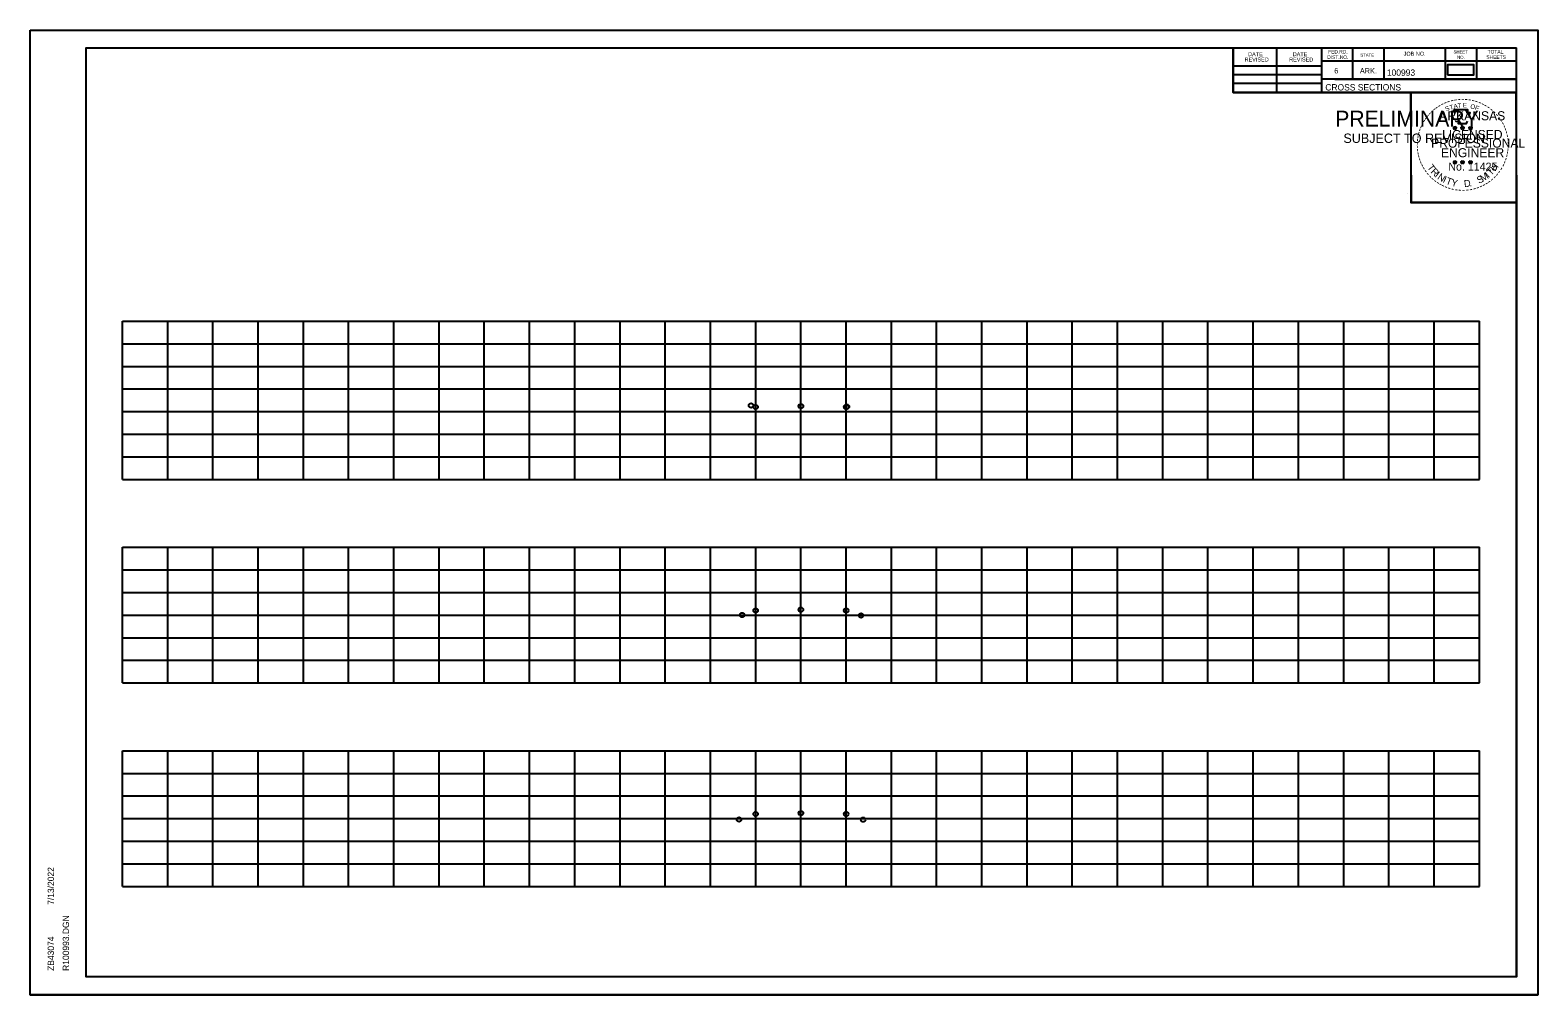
# Model space of a CAD drawing. Extents: x 4667 to 1632277, y -2100 to 724501.
# Drawn here: x 7113.9 to 7447.2, y -782.3 to -569 of the extents above; entities that cross this region are included whole.
import ezdxf

# ---------------------------------------------------------------- set-up
doc = ezdxf.new("R2010")
doc.units = 0
doc.layers.add('R_Grid', color=7, linetype='Continuous')
doc.layers.add('R_No Plot', color=7, linetype='Continuous')

msp = doc.modelspace()

# ---------------------------------------------------------------- linework, layer by layer
at = {"layer": 'R_Grid'}
for p, q in [((7134.28, -633.33), (7434.28, -633.33)), ((7134.28, -668.33), (7134.28, -633.33)), ((7144.28, -668.33), (7144.28, -633.33)), ((7154.28, -668.33), (7154.28, -633.33)), ((7164.28, -668.33), (7164.28, -633.33)), ((7174.28, -668.33), (7174.28, -633.33)), ((7184.28, -668.33), (7184.28, -633.33)), ((7194.28, -668.33), (7194.28, -633.33)), ((7204.28, -668.33), (7204.28, -633.33)), ((7214.28, -668.33), (7214.28, -633.33)), ((7224.28, -668.33), (7224.28, -633.33)), ((7234.28, -668.33), (7234.28, -633.33)), ((7244.28, -668.33), (7244.28, -633.33)), ((7254.28, -668.33), (7254.28, -633.33)), ((7264.28, -668.33), (7264.28, -633.33)), ((7274.28, -668.33), (7274.28, -633.33)), ((7284.28, -668.33), (7284.28, -633.33)), ((7294.28, -668.33), (7294.28, -633.33)), ((7304.28, -668.33), (7304.28, -633.33)), ((7314.28, -668.33), (7314.28, -633.33)), ((7324.28, -668.33), (7324.28, -633.33)), ((7334.28, -668.33), (7334.28, -633.33)), ((7344.28, -668.33), (7344.28, -633.33)), ((7354.28, -668.33), (7354.28, -633.33)), ((7364.28, -668.33), (7364.28, -633.33)), ((7374.28, -668.33), (7374.28, -633.33)), ((7384.28, -668.33), (7384.28, -633.33)), ((7394.28, -668.33), (7394.28, -633.33)), ((7404.28, -668.33), (7404.28, -633.33)), ((7414.28, -668.33), (7414.28, -633.33)), ((7424.28, -668.33), (7424.28, -633.33)), ((7434.28, -668.33), (7434.28, -633.33)), ((7134.28, -638.33), (7434.28, -638.33)), ((7134.28, -643.33), (7434.28, -643.33)), ((7134.28, -648.33), (7434.28, -648.33)), ((7134.28, -653.33), (7434.28, -653.33)), ((7134.28, -658.33), (7434.28, -658.33)), ((7134.28, -663.33), (7434.28, -663.33)), ((7134.28, -668.33), (7434.28, -668.33)), ((7134.28, -683.33), (7434.28, -683.33)), ((7134.28, -713.33), (7134.28, -683.33)), ((7144.28, -713.33), (7144.28, -683.33)), ((7154.28, -713.33), (7154.28, -683.33)), ((7164.28, -713.33), (7164.28, -683.33)), ((7174.28, -713.33), (7174.28, -683.33)), ((7184.28, -713.33), (7184.28, -683.33)), ((7194.28, -713.33), (7194.28, -683.33)), ((7204.28, -713.33), (7204.28, -683.33)), ((7214.28, -713.33), (7214.28, -683.33)), ((7224.28, -713.33), (7224.28, -683.33)), ((7234.28, -713.33), (7234.28, -683.33)), ((7244.28, -713.33), (7244.28, -683.33)), ((7254.28, -713.33), (7254.28, -683.33)), ((7264.28, -713.33), (7264.28, -683.33)), ((7274.28, -713.33), (7274.28, -683.33)), ((7284.28, -713.33), (7284.28, -683.33)), ((7294.28, -713.33), (7294.28, -683.33)), ((7304.28, -713.33), (7304.28, -683.33)), ((7314.28, -713.33), (7314.28, -683.33)), ((7324.28, -713.33), (7324.28, -683.33)), ((7334.28, -713.33), (7334.28, -683.33)), ((7344.28, -713.33), (7344.28, -683.33)), ((7354.28, -713.33), (7354.28, -683.33)), ((7364.28, -713.33), (7364.28, -683.33)), ((7374.28, -713.33), (7374.28, -683.33)), ((7384.28, -713.33), (7384.28, -683.33)), ((7394.28, -713.33), (7394.28, -683.33)), ((7404.28, -713.33), (7404.28, -683.33)), ((7414.28, -713.33), (7414.28, -683.33)), ((7424.28, -713.33), (7424.28, -683.33)), ((7434.28, -713.33), (7434.28, -683.33)), ((7134.28, -688.33), (7434.28, -688.33)), ((7134.28, -693.33), (7434.28, -693.33)), ((7134.28, -698.33), (7434.28, -698.33)), ((7134.28, -703.33), (7434.28, -703.33)), ((7134.28, -708.33), (7434.28, -708.33)), ((7134.28, -713.33), (7434.28, -713.33)), ((7134.28, -728.33), (7434.28, -728.33)), ((7134.28, -758.33), (7134.28, -728.33)), ((7144.28, -758.33), (7144.28, -728.33)), ((7154.28, -758.33), (7154.28, -728.33)), ((7164.28, -758.33), (7164.28, -728.33)), ((7174.28, -758.33), (7174.28, -728.33)), ((7184.28, -758.33), (7184.28, -728.33)), ((7194.28, -758.33), (7194.28, -728.33)), ((7204.28, -758.33), (7204.28, -728.33)), ((7214.28, -758.33), (7214.28, -728.33)), ((7224.28, -758.33), (7224.28, -728.33)), ((7234.28, -758.33), (7234.28, -728.33)), ((7244.28, -758.33), (7244.28, -728.33)), ((7254.28, -758.33), (7254.28, -728.33)), ((7264.28, -758.33), (7264.28, -728.33)), ((7274.28, -758.33), (7274.28, -728.33)), ((7284.28, -758.33), (7284.28, -728.33)), ((7294.28, -758.33), (7294.28, -728.33)), ((7304.28, -758.33), (7304.28, -728.33)), ((7314.28, -758.33), (7314.28, -728.33)), ((7324.28, -758.33), (7324.28, -728.33)), ((7334.28, -758.33), (7334.28, -728.33)), ((7344.28, -758.33), (7344.28, -728.33)), ((7354.28, -758.33), (7354.28, -728.33)), ((7364.28, -758.33), (7364.28, -728.33)), ((7374.28, -758.33), (7374.28, -728.33)), ((7384.28, -758.33), (7384.28, -728.33)), ((7394.28, -758.33), (7394.28, -728.33)), ((7404.28, -758.33), (7404.28, -728.33)), ((7414.28, -758.33), (7414.28, -728.33)), ((7424.28, -758.33), (7424.28, -728.33)), ((7434.28, -758.33), (7434.28, -728.33)), ((7134.28, -733.33), (7434.28, -733.33)), ((7134.28, -738.33), (7434.28, -738.33)), ((7134.28, -743.33), (7434.28, -743.33)), ((7134.28, -748.33), (7434.28, -748.33)), ((7134.28, -753.33), (7434.28, -753.33)), ((7134.28, -758.33), (7434.28, -758.33))]:
    msp.add_line(p, q, dxfattribs=at)
at = {"layer": 'R_No Plot'}
for p, q in [((7113.88, -568.98), (7447.21, -568.98)), ((7126.28, -572.87), (7442.46, -572.87)), ((7126.28, -778.33), (7126.28, -572.87)), ((7278.8, -573.13), (7278.8, -573.13)), ((7278.8, -573.13), (7278.8, -573.13)), ((7379.82, -582.75), (7379.82, -572.87)), ((7389.5, -582.75), (7389.5, -572.87)), ((7399.36, -572.87), (7399.36, -582.75)), ((7406.2, -572.87), (7406.2, -579.81)), ((7413.14, -572.87), (7413.14, -579.81)), ((7426.72, -572.87), (7426.72, -579.81)), ((7433.66, -572.87), (7433.66, -579.81)), ((7442.46, -778.33), (7442.46, -572.87)), ((7442.46, -575.81), (7399.36, -575.81)), ((7442.46, -575.79), (7442.46, -575.79)), ((7379.82, -576.89), (7399.36, -576.89)), ((7379.82, -578.75), (7399.36, -578.75)), ((7442.46, -579.81), (7399.36, -579.81)), ((7402.32, -579.81), (7442.46, -579.81)), ((7379.82, -580.69), (7399.36, -580.69)), ((7442.46, -582.75), (7379.82, -582.75)), ((7428.54, -590.5), (7428.89, -590.61)), ((7428.54, -590.5), (7428.79, -590.54)), ((7428.54, -590.5), (7428.78, -590.62)), ((7428.67, -590.9), (7428.89, -590.61)), ((7428.67, -590.9), (7428.8, -590.66)), ((7428.67, -590.9), (7428.89, -590.69)), ((7428.89, -590.24), (7428.85, -590.49)), ((7428.89, -590.61), (7428.89, -590.24)), ((7428.89, -590.24), (7428.94, -590.49)), ((7429.24, -590.5), (7428.89, -590.61)), ((7429.1, -590.9), (7428.89, -590.61)), ((7429.1, -590.9), (7428.89, -590.69)), ((7429.24, -590.5), (7428.95, -590.54)), ((7429.1, -590.9), (7428.97, -590.61)), ((7429.24, -590.5), (7429.03, -590.6)), ((7430.21, -590.5), (7430.56, -590.61)), ((7430.21, -590.5), (7430.46, -590.54)), ((7430.21, -590.5), (7430.45, -590.62)), ((7430.34, -590.9), (7430.56, -590.61)), ((7430.34, -590.9), (7430.47, -590.66)), ((7430.34, -590.9), (7430.56, -590.69)), ((7430.56, -590.24), (7430.52, -590.49)), ((7430.56, -590.61), (7430.56, -590.24)), ((7430.56, -590.24), (7430.61, -590.49)), ((7430.91, -590.5), (7430.56, -590.61)), ((7430.77, -590.9), (7430.56, -590.61)), ((7430.77, -590.9), (7430.56, -590.69)), ((7430.91, -590.5), (7430.62, -590.54)), ((7430.77, -590.9), (7430.64, -590.61)), ((7430.91, -590.5), (7430.7, -590.6)), ((7431.98, -590.51), (7432.32, -590.62)), ((7431.98, -590.51), (7432.23, -590.55)), ((7431.98, -590.51), (7432.21, -590.63)), ((7432.11, -590.92), (7432.32, -590.62)), ((7432.11, -590.92), (7432.23, -590.67)), ((7432.11, -590.92), (7432.32, -590.7)), ((7432.32, -590.25), (7432.28, -590.51)), ((7432.32, -590.62), (7432.32, -590.25)), ((7432.32, -590.25), (7432.37, -590.5)), ((7432.67, -590.51), (7432.32, -590.62)), ((7432.54, -590.92), (7432.32, -590.62)), ((7432.54, -590.92), (7432.32, -590.7)), ((7432.67, -590.51), (7432.39, -590.56)), ((7432.54, -590.92), (7432.4, -590.62)), ((7432.67, -590.51), (7432.47, -590.61)), ((7428.54, -598.07), (7428.89, -598.18)), ((7428.54, -598.07), (7428.79, -598.11)), ((7428.54, -598.07), (7428.77, -598.19)), ((7428.67, -598.48), (7428.89, -598.18)), ((7428.67, -598.48), (7428.8, -598.23)), ((7428.67, -598.48), (7428.88, -598.26)), ((7428.89, -597.81), (7428.85, -598.07)), ((7429.1, -598.48), (7428.88, -598.26)), ((7428.89, -598.18), (7428.89, -597.81)), ((7428.89, -597.81), (7428.94, -598.06)), ((7429.23, -598.07), (7428.89, -598.18)), ((7429.1, -598.48), (7428.89, -598.18)), ((7429.23, -598.07), (7428.95, -598.12)), ((7429.1, -598.48), (7428.96, -598.19)), ((7429.23, -598.07), (7429.03, -598.17)), ((7430.21, -598.07), (7430.56, -598.18)), ((7430.21, -598.07), (7430.46, -598.11)), ((7430.21, -598.07), (7430.44, -598.19)), ((7430.34, -598.48), (7430.56, -598.18)), ((7430.34, -598.48), (7430.47, -598.23)), ((7430.34, -598.48), (7430.55, -598.26)), ((7430.56, -597.81), (7430.51, -598.07)), ((7430.77, -598.48), (7430.55, -598.26)), ((7430.56, -598.18), (7430.56, -597.81)), ((7430.56, -597.81), (7430.6, -598.06)), ((7430.9, -598.07), (7430.56, -598.18)), ((7430.77, -598.48), (7430.56, -598.18)), ((7430.9, -598.07), (7430.62, -598.12)), ((7430.77, -598.48), (7430.63, -598.19)), ((7430.9, -598.07), (7430.7, -598.17)), ((7431.97, -598.08), (7432.32, -598.19)), ((7431.97, -598.08), (7432.23, -598.12)), ((7431.97, -598.08), (7432.21, -598.2)), ((7432.11, -598.49), (7432.32, -598.19)), ((7432.11, -598.49), (7432.23, -598.24)), ((7432.11, -598.49), (7432.32, -598.27)), ((7432.32, -597.82), (7432.28, -598.08)), ((7432.32, -598.19), (7432.32, -597.82)), ((7432.32, -597.82), (7432.37, -598.07)), ((7432.67, -598.08), (7432.32, -598.19)), ((7432.54, -598.49), (7432.32, -598.19)), ((7432.54, -598.49), (7432.32, -598.27)), ((7432.67, -598.08), (7432.38, -598.13)), ((7432.54, -598.49), (7432.4, -598.2)), ((7432.67, -598.08), (7432.47, -598.18)), ((7418.49, -605.21), (7418.49, -605.21)), ((7126.28, -778.33), (7126.28, -778.33)), ((7442.46, -778.33), (7126.28, -778.33)), ((7113.88, -782.31), (7447.21, -782.31))]:
    msp.add_line(p, q, dxfattribs=at)
for points in [[(7113.87, -568.98), (7447.21, -568.98), (7447.21, -782.31), (7113.87, -782.31)], [(7360.2, -572.87), (7379.82, -572.87), (7379.82, -582.75), (7395.93, -582.75), (7419.13, -582.75), (7419.13, -607.08), (7442.46, -607.08), (7442.46, -778.33), (7126.28, -778.33), (7126.28, -572.87)], [(7427.22, -578.86), (7433.06, -578.86), (7433.06, -576.67), (7427.22, -576.67)], [(7419.13, -582.75), (7442.34, -582.75), (7442.46, -607.08), (7419.25, -607.08)]]:
    msp.add_lwpolyline(points, close=True, dxfattribs=at)
for points in [[(7428.58, -586.62), (7428.85, -587.44)], [(7432.09, -587.54), (7432.24, -587.26), (7431.55, -587.28), (7431.7, -586.62), (7428.58, -586.62)], [(7429.07, -589.04), (7429.07, -589.13), (7429.64, -589.15), (7429.58, -589.62), (7431.45, -589.62), (7431.65, -589.08)], [(7428.89, -590.24), (7429.1, -590.9), (7428.54, -590.5), (7429.24, -590.5), (7428.67, -590.9), (7428.89, -590.24)], [(7430.56, -590.24), (7430.77, -590.9), (7430.21, -590.5), (7430.91, -590.5), (7430.34, -590.9), (7430.56, -590.24)], [(7432.32, -590.25), (7432.54, -590.92), (7431.98, -590.51), (7432.67, -590.51), (7432.11, -590.92), (7432.32, -590.25)], [(7428.89, -597.81), (7429.1, -598.48), (7428.54, -598.07), (7429.23, -598.07), (7428.67, -598.48), (7428.89, -597.81)], [(7430.56, -597.81), (7430.77, -598.48), (7430.21, -598.07), (7430.9, -598.07), (7430.34, -598.48), (7430.56, -597.81)], [(7432.32, -597.82), (7432.54, -598.49), (7431.97, -598.08), (7432.67, -598.08), (7432.11, -598.49), (7432.32, -597.82)]]:
    msp.add_lwpolyline(points, dxfattribs=at)
for centre, radius in [((7428.89, -590.61), 0.172), ((7428.89, -590.61), 0.145), ((7428.89, -590.61), 0.116), ((7428.89, -590.61), 0.0991), ((7428.89, -590.61), 0.0747), ((7428.89, -590.61), 0.0495), ((7428.89, -590.61), 0.0296), ((7430.56, -590.61), 0.172), ((7430.56, -590.61), 0.145), ((7430.56, -590.61), 0.116), ((7430.56, -590.61), 0.0991), ((7430.56, -590.61), 0.0747), ((7430.56, -590.61), 0.0495), ((7430.56, -590.61), 0.0296), ((7432.32, -590.62), 0.172), ((7432.32, -590.62), 0.145), ((7432.32, -590.62), 0.116), ((7432.32, -590.62), 0.0991), ((7432.32, -590.62), 0.0747), ((7432.32, -590.62), 0.0495), ((7432.32, -590.62), 0.0296), ((7428.89, -598.18), 0.172), ((7428.89, -598.18), 0.145), ((7428.89, -598.18), 0.116), ((7428.89, -598.18), 0.0991), ((7428.89, -598.18), 0.0747), ((7428.89, -598.18), 0.0495), ((7428.89, -598.18), 0.0296), ((7430.55, -598.18), 0.172), ((7430.55, -598.18), 0.145), ((7430.55, -598.18), 0.116), ((7430.55, -598.18), 0.0991), ((7430.55, -598.18), 0.0747), ((7430.55, -598.18), 0.0495), ((7430.55, -598.18), 0.0296), ((7432.32, -598.19), 0.172), ((7432.32, -598.19), 0.145), ((7432.32, -598.19), 0.116), ((7432.32, -598.19), 0.0991), ((7432.32, -598.19), 0.0747), ((7432.32, -598.19), 0.0495), ((7432.32, -598.19), 0.0296), ((7273.25, -651.98), 0.5), ((7274.28, -652.32), 0.5), ((7284.28, -652.12), 0.5), ((7294.28, -652.32), 0.5), ((7294.48, -652.25), 0.5), ((7284.28, -697.12), 0.5), ((7271.29, -698.31), 0.5), ((7274.28, -697.32), 0.5), ((7294.28, -697.32), 0.5), ((7297.57, -698.41), 0.5), ((7270.6, -743.54), 0.5), ((7274.28, -742.32), 0.5), ((7284.28, -742.12), 0.5), ((7294.28, -742.32), 0.5), ((7298.06, -743.58), 0.5)]:
    msp.add_circle(centre, radius, dxfattribs=at)

# ---------------------------------------------------------------- texts
for s, height, rotation, p in [('REVISED', 0.879, 360, (7382.37, -575.91)), ('DATE', 0.879, 360, (7383.15, -574.73)), ('REVISED', 0.879, 360, (7392.23, -575.91)), ('DATE', 0.879, 360, (7393.01, -574.73)), ('DIST.NO.', 0.782, 360, (7400.64, -575.33)), ('FED.RD.', 0.782, 360, (7400.84, -574.15)), ('STATE', 0.684, 360, (7407.96, -574.83)), ('JOB NO.', 0.879, 360, (7417.54, -574.63)), ('SHEET', 0.684, 360, (7428.58, -574.15)), ('NO.', 0.684, 360, (7429.36, -575.33)), ('SHEETS', 0.782, 360, (7435.82, -575.33)), ('TOTAL', 0.782, 360, (7436.1, -574.15)), ('6', 1.17, 360, (7402.2, -578.55)), ('ARK.', 1.172, 360, (7407.86, -578.55)), ('100993', 1.4, 360, (7413.83, -579.07)), ('CROSS SECTIONS', 1.4, 360, (7400.22, -582.32)), ('-', 1.6, 38.9507, (7424.41, -587.22)), ('-', 1.6, 36.2317, (7424.89, -586.84)), ('-', 1.6, 34.0636, (7425.47, -586.45)), ('-', 1.6, 28.7918, (7426.06, -586.08)), ('-', 1.6, 24.3072, (7426.7, -585.76)), ('S', 1, 21.594, (7426.94, -586.94)), ('-', 1.6, 19.1761, (7427.33, -585.49)), ('T', 1, 16.4036, (7427.85, -586.61)), ('-', 1.6, 13.6301, (7428.08, -585.25)), ('A', 1, 11.2132, (7428.68, -586.36)), ('-', 1.6, 10.2193, (7428.76, -585.09)), ('T', 1, 6.0228, (7429.53, -586.19)), ('-', 1.6, 5.8968, (7429.49, -584.98)), ('-', 1.6, 0.1862, (7430.26, -584.91)), ('E', 1, 0.8323, (7430.63, -586.08)), ('-', 1.6, 357.743, (7430.98, -584.92)), ('-', 1.6, 352.1617, (7431.73, -584.97)), ('O', 1, 350.4515, (7432.23, -586.29)), ('-', 1.6, 347.2049, (7432.44, -585.09)), ('F', 1, 340.0707, (7433.19, -586.52)), ('-', 1.6, 342.3362, (7433.08, -585.24)), ('-', 1.6, 337.8551, (7433.81, -585.47)), ('-', 1.6, 334.1211, (7434.45, -585.74)), ('-', 1.6, 329.6409, (7435.02, -586.02)), ('-', 1.6, 325.8627, (7435.67, -586.38)), ('-', 1.6, 320.5297, (7436.28, -586.81)), ('PRELIMINARY', 3.5, 360, (7402.41, -590.29)), ('DWB', 0.01, 360, (7403.15, -588.44)), ('-', 1.6, 62.8713, (7422.08, -590.31)), ('-', 1.6, 58.0706, (7422.39, -589.69)), ('-', 1.6, 54.2325, (7422.71, -589.17)), ('-', 1.6, 50.6142, (7423.13, -588.6)), ('-', 1.6, 48.423, (7423.53, -588.11)), ('-', 1.6, 42.9622, (7423.98, -587.64)), ('ARKANSAS', 2, 360, (7425.43, -588.91)), ('-', 1.6, 315.5786, (7436.88, -587.3)), ('-', 1.6, 309.8797, (7437.45, -587.85)), ('-', 1.6, 306.6522, (7437.97, -588.45)), ('-', 1.4, 303.6753, (7438.46, -589.02)), ('-', 1.6, 299.6684, (7438.78, -589.62)), ('SUBJECT TO REVISION', 2.0751, 360, (7404.22, -593.92)), ('-', 1.6, 85.1863, (7421.19, -593.67)), ('-', 1.6, 81.2013, (7421.27, -592.98)), ('-', 1.6, 75.461, (7421.4, -592.26)), ('-', 1.6, 72.3945, (7421.6, -591.55)), ('-', 1.6, 67.7743, (7421.82, -590.92)), ('PROFESSIONAL', 2, 360, (7423.61, -594.96)), ('LICENSED', 2, 360, (7426.03, -593.05)), ('DWB', 0.01, 360, (7428.88, -590.61)), ('DWB', 0.01, 360, (7430.55, -590.61)), ('DWB', 0.01, 360, (7432.31, -590.62)), ('-', 1.6, 294.6628, (7439.1, -590.23)), ('-', 1.6, 290.5728, (7439.36, -590.81)), ('-', 1.6, 285.1233, (7439.59, -591.39)), ('-', 1.6, 280.5493, (7439.79, -592.13)), ('-', 1.6, 276.5962, (7439.95, -592.9)), ('-', 1.6, 94.1959, (7421.2, -595.09)), ('-', 1.6, 89.0622, (7421.17, -594.37)), ('-', 1.6, 98.9479, (7421.28, -595.76)), ('-', 1.6, 101.7149, (7421.41, -596.49)), ('-', 1.6, 105.4578, (7421.57, -597.09)), ('ENGINEER', 2, 360, (7425.8, -597.08)), ('-', 1.6, 255.7626, (7439.85, -596.25)), ('-', 1.6, 260.9953, (7439.96, -595.58)), ('-', 1.6, 263.5172, (7440.03, -594.92)), ('-', 1.6, 274.3301, (7440.01, -593.62)), ('-', 1.6, 269.9407, (7440.05, -594.26)), ('-', 1.6, 109.0874, (7421.79, -597.72)), ('-', 1.6, 114.0643, (7422.04, -598.32)), ('-', 1.6, 115.7289, (7422.35, -598.93)), ('-', 1.6, 120.4471, (7422.7, -599.52)), ('-', 1.6, 125.8934, (7423.11, -600.08)), ('T', 1.54, 306.0406, (7422.65, -599.34)), ('R', 1.54, 314.005, (7423.41, -600.39)), ('No. 11425', 1.757, 360, (7427.42, -600.03)), ('DWB', 0.01, 360, (7428.87, -598.18)), ('DWB', 0.01, 360, (7430.54, -598.18)), ('DWB', 0.01, 360, (7432.31, -598.19)), ('T', 1.54, 46.6444, (7436.88, -601.25)), ('H', 1.54, 54.6088, (7437.77, -600.31)), ('-', 1.6, 239.0712, (7438.79, -599.03)), ('-', 1.6, 244.6197, (7439.18, -598.28)), ('-', 1.6, 247.8887, (7439.44, -597.65)), ('-', 1.6, 252.8681, (7439.67, -596.97)), ('-', 1.6, 130.7181, (7423.57, -600.63)), ('-', 1.6, 134.2238, (7424.09, -601.18)), ('-', 1.6, 138.9338, (7424.61, -601.64)), ('-', 1.6, 144.6463, (7425.17, -602.05)), ('I', 1.54, 321.9694, (7424.31, -601.32)), ('-', 1.6, 148.0898, (7425.73, -602.42)), ('N', 1.54, 326.5002, (7424.88, -601.79)), ('-', 1.6, 151.5704, (7426.31, -602.74)), ('-', 1.6, 154.6002, (7426.83, -602.99)), ('I', 1.54, 335.3603, (7426.08, -602.58)), ('T', 1.54, 339.8912, (7426.74, -602.91)), ('Y', 1.54, 347.8556, (7427.96, -603.35)), ('D', 1.54, 6.3969, (7430.95, -603.71)), ('.', 1.54, 13.7642, (7432.14, -603.58)), ('S', 1.54, 26.9312, (7434.19, -602.98)), ('M', 1.54, 32.6563, (7435.03, -602.57)), ('-', 1.6, 207.3568, (7435.31, -602.52)), ('I', 1.54, 42.1136, (7436.31, -601.73)), ('-', 1.6, 212.2491, (7435.87, -602.18)), ('-', 1.6, 215.7363, (7436.4, -601.79)), ('-', 1.6, 221.0851, (7436.95, -601.32)), ('-', 1.6, 225.7653, (7437.48, -600.81)), ('-', 1.6, 231.2538, (7437.95, -600.25)), ('-', 1.6, 233.8452, (7438.38, -599.68)), ('-', 1.6, 158.5612, (7427.45, -603.24)), ('-', 1.6, 162.7983, (7428.14, -603.46)), ('-', 1.6, 167.5555, (7428.85, -603.62)), ('-', 1.6, 173.1155, (7429.63, -603.73)), ('-', 1.6, 176.5183, (7430.37, -603.78)), ('-', 1.6, 181.5918, (7431.12, -603.77)), ('-', 1.6, 185.8167, (7431.93, -603.69)), ('-', 1.6, 191.2858, (7432.66, -603.56)), ('-', 1.6, 195.4743, (7433.39, -603.36)), ('-', 1.6, 200.7184, (7434.07, -603.12)), ('-', 1.6, 204.2516, (7434.69, -602.84)), ('7/13/2022', 1.4, 90, (7119.14, -762.4)), ('R100993.DGN', 1.4, 90, (7122.47, -777.01)), ('ZB43074', 1.4, 90, (7119.14, -777.01))]:
    msp.add_text(s, height=height, rotation=rotation, dxfattribs=at).set_placement(p)

doc.saveas('drawing.dxf')
